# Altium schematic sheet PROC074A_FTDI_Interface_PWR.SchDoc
size 431 x 279 mm; Date: Not shown in title block; ApprovedBy: Not shown in title block; CheckedBy: Not shown in title block; Author: Not shown in title block; CompanyName: Not shown in title block; Engineer: Not shown in title block; Organization: Not shown in title block; Address1: Not shown in title block; Address2: Not shown in title block; Address3: Not shown in title block; Address4: Not shown in title block; DocumentNumber: 1; Revision: Use project parameter SCH_Rev; SheetNumber: 17; SheetTotal: 22; PageSetup: Record=PageOptions¦CenterHorizontal=True¦CenterVertical=True¦PrintScale=1.00¦XCorrection=1.00¦YCorrection=1.00¦PrintKind=0¦BorderSize=5000000¦LeftOffset=0¦BottomOffset=0¦Orientation=2¦PaperLength=1000¦PaperWidth=1000¦Scale=100¦PaperSource=15¦PrintQuality=600¦MediaType=1¦DitherType=10¦PaperKind=Letter¦PrintScaleMode=1
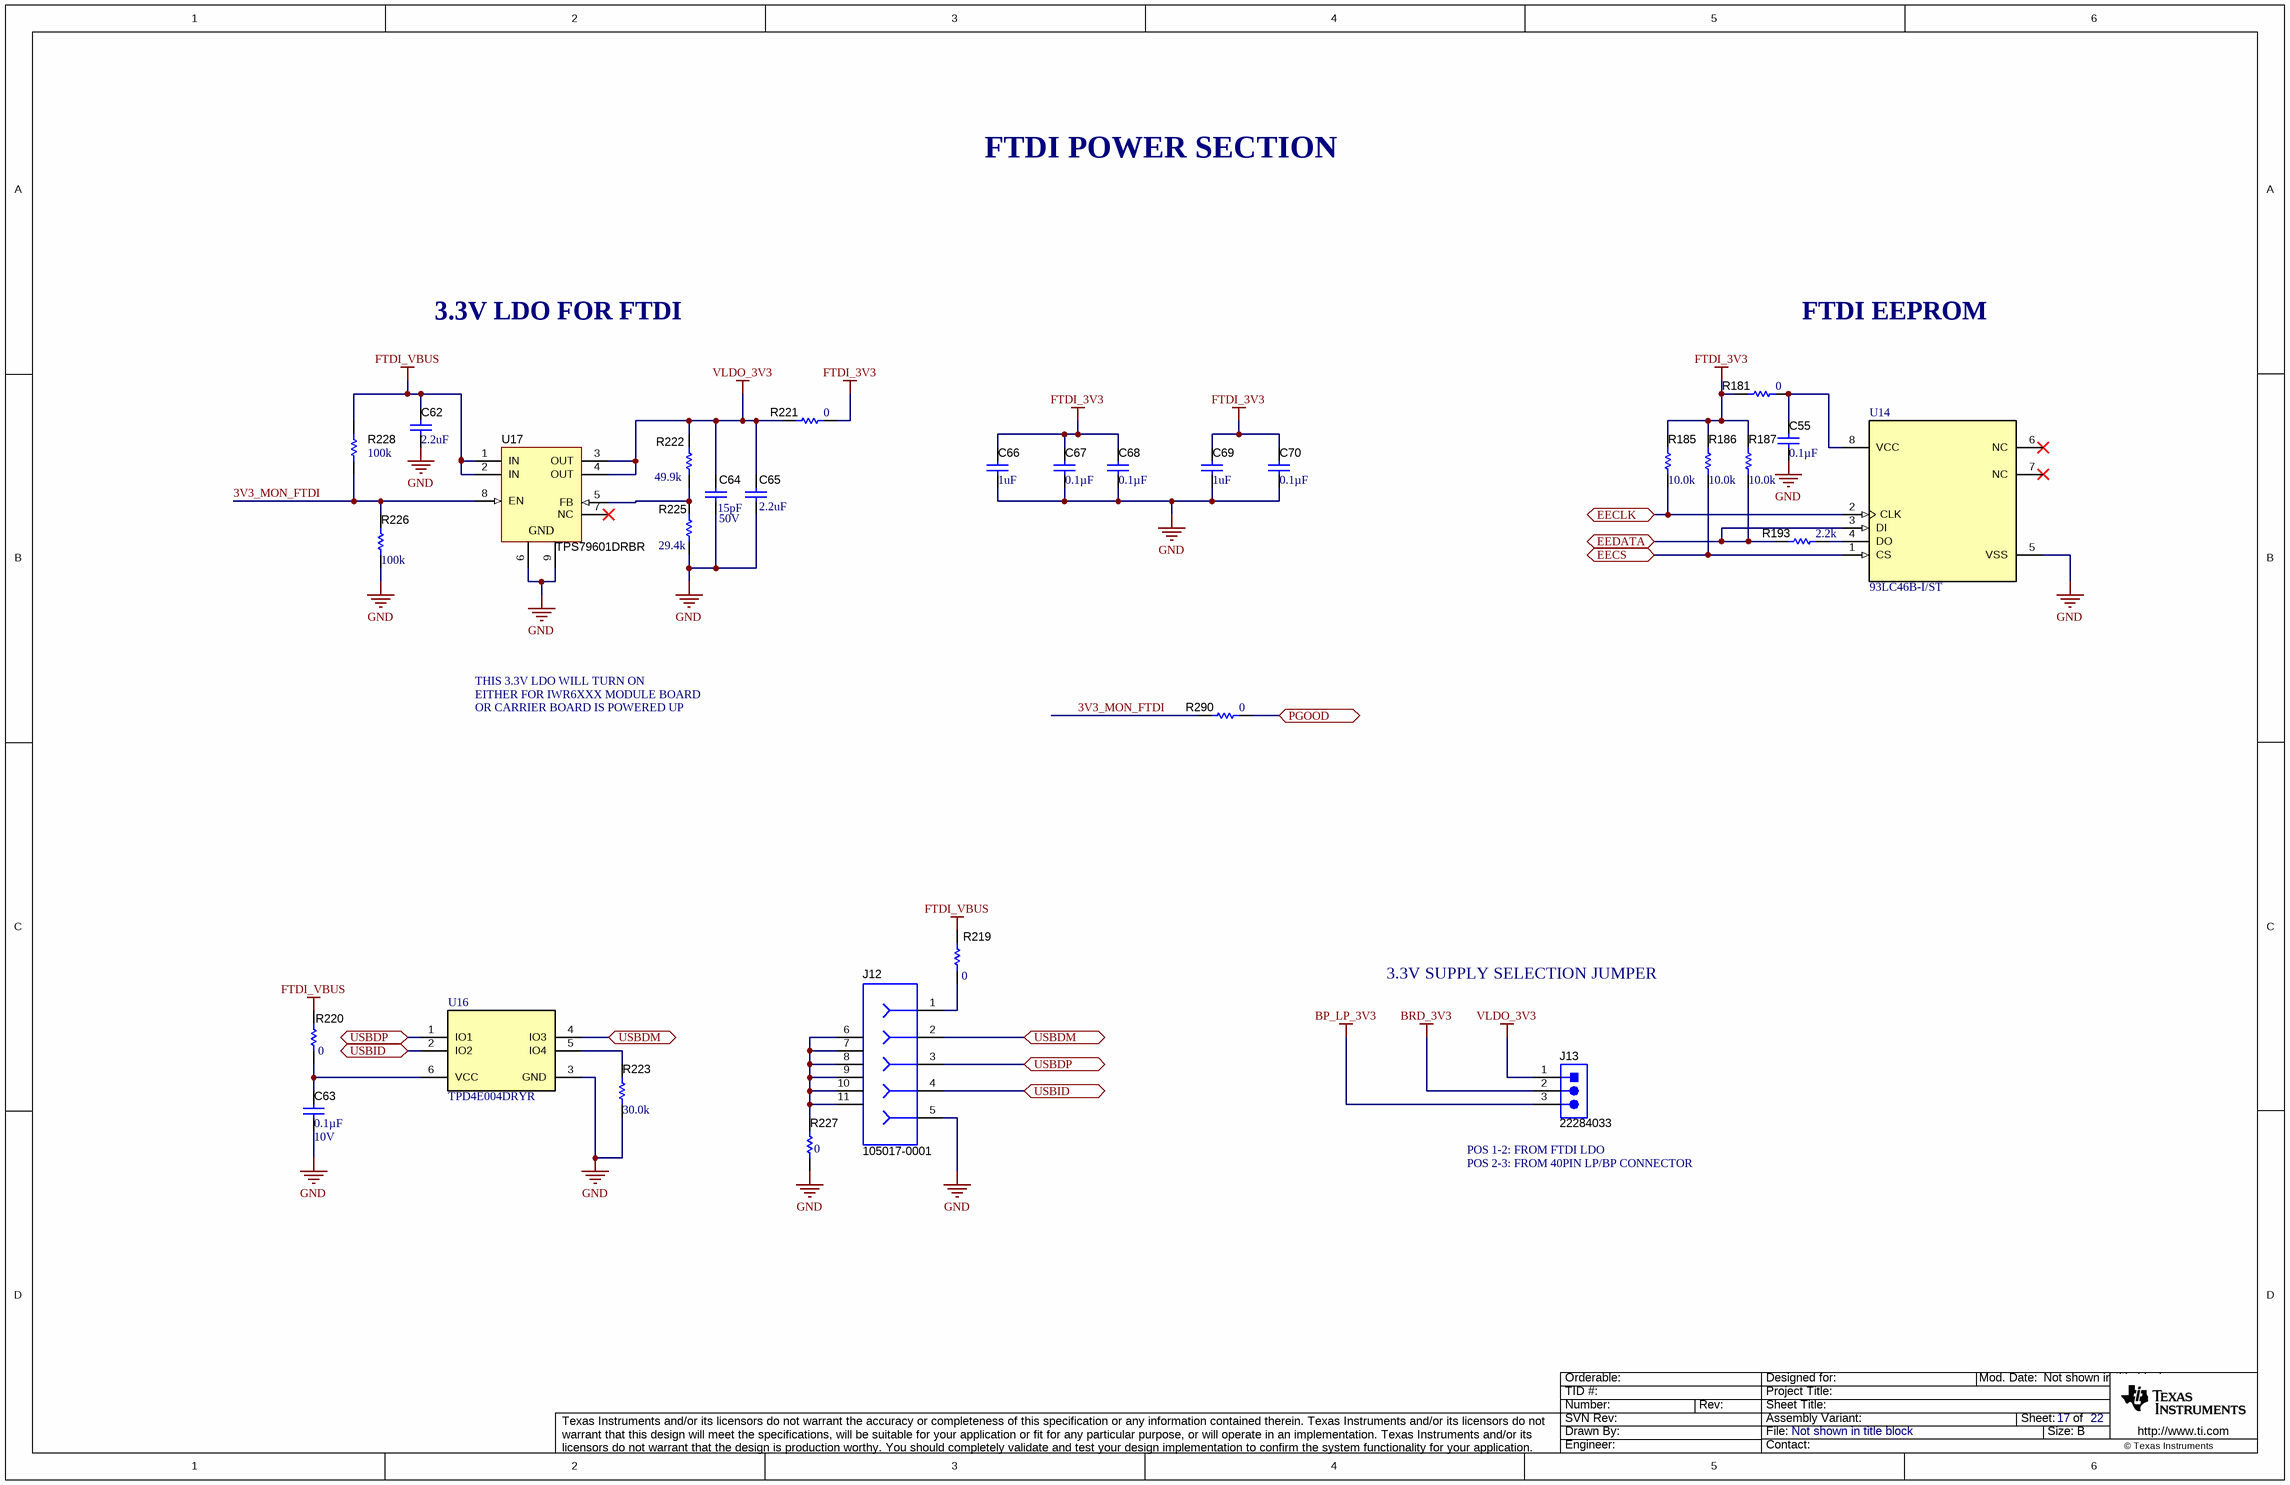
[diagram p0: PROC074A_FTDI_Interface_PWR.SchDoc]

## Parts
C55  ValueDisplayed: 0.1µF  [0402]  (hidden comment: C0402C104K8RACTU)
C62  ValueDisplayed: 2.2uF  [0402_065]  (hidden comment: C1005X7S1A225K050BC)
C63  VDC_V: 10V  ValueDisplayed: 0.1µF  [0402]  (hidden comment: C0402C104K8RACTU)
C64  VDC_V: 50V  ValueDisplayed: 15pF  [0402]  (hidden comment: 04025A150FAT2A)
C65  ValueDisplayed: 2.2uF  [0402_065]  (hidden comment: C1005X7S1A225K050BC)
C66  ValueDisplayed: 1uF  [0603]  (hidden comment: GCM188R71C105KA64D)
C67  ValueDisplayed: 0.1µF  [0402]  (hidden comment: C0402C104K8RACTU)
C68  ValueDisplayed: 0.1µF  [0402]  (hidden comment: C0402C104K8RACTU)
C69  ValueDisplayed: 1uF  [0603]  (hidden comment: GCM188R71C105KA64D)
C70  ValueDisplayed: 0.1µF  [0402]  (hidden comment: C0402C104K8RACTU)
J12  105017-0001  [CONN_105017-0001]
J13  22284033  [Molex_0022284033]
R181  ValueDisplayed: 0  [0402]  (hidden comment: ERJ-2GE0R00X)
R185  ValueDisplayed: 10.0k  [0402]  (hidden comment: CRCW040210K0FKED)
R186  ValueDisplayed: 10.0k  [0402]  (hidden comment: CRCW040210K0FKED)
R187  ValueDisplayed: 10.0k  [0402]  (hidden comment: CRCW040210K0FKED)
R193  ValueDisplayed: 2.2k  [0402]  (hidden comment: CRCW04022K20JNED)
R219  ValueDisplayed: 0  [0805_HV]  (hidden comment: CRCW08050000Z0EA)
R220  ValueDisplayed: 0  [0805]  (hidden comment: CRCW08050000Z0EA)
R221  ValueDisplayed: 0  [0805]  (hidden comment: CRCW08050000Z0EA)
R222  ValueDisplayed: 49.9k  [0402]  (hidden comment: CRCW040249K9FKED)
R223  ValueDisplayed: 30.0k  [0402]  (hidden comment: CRCW040230K0FKED)
R225  ValueDisplayed: 29.4k  [0402]  (hidden comment: CRCW040229K4FKED)
R226  ValueDisplayed: 100k  [0402]  (hidden comment: CRCW0402100KFKED)
R227  ValueDisplayed: 0  [0402]  (hidden comment: ERJ-2GE0R00X)
R228  ValueDisplayed: 100k  [0402]  (hidden comment: CRCW0402100KFKED)
R290  ValueDisplayed: 0  [0402]  (hidden comment: ERJ-2GE0R00X)
U14  93LC46B-I/ST  [TSSOP-8]
U16  TPD4E004DRYR  [DRY0006A]
U17  TPS79601DRBR  [DRB0008B]

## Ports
EECLK, EECS, EEDATA, PGOOD, USBDM, USBDP, USBID

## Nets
BP_LP_3V3: J13.3
BRD_3V3: J13.2
FTDI_3V3: C66.1 C67.1 C68.1 C69.1 C70.1 R181.2 R185.2 R186.2 R187.2 R221.2
FTDI_VBUS: C62.1 R219.2 R220.2 R228.2 U17.1(IN) U17.2(IN)
GND: C55.2 C62.2 C63.2 C64.2 C65.2 C66.2 C67.2 C68.2 C69.2 C70.2 J12.5 R223.1 R225.2 R226.1 R227.1 U14.5(VSS) U16.3(GND) U17.6(GND) U17.9(GND)
VLDO_3V3: C64.1 C65.1 J13.1 R221.1 R222.2 U17.3(OUT) U17.4(OUT)
3V3_MON_FTDI: R226.2 R228.1 R290.1 U17.8(EN)
EECLK: R185.1 U14.2(CLK) ; port EECLK
EECS: R186.1 U14.1(CS) ; port EECS
EEDATA: R187.1 R193.1 U14.3(DI) ; port EEDATA
PGOOD: R290.2 ; port PGOOD
USBDM: J12.2 U16.4(IO3) ; port USBDM
USBDP: J12.3 U16.1(IO1) ; port USBDP
USBID: J12.4 U16.2(IO2) ; port USBID
NetC55_1: C55.1 R181.1 U14.8(VCC)
NetC63_1: C63.1 R220.1 U16.6(VCC)
NetJ12_1: J12.1 R219.1
NetJ12_6: J12.6 J12.7 J12.8 J12.9 J12.10 J12.11 R227.2
NetR193_2: R193.2 U14.4(DO)
NetR222_1: R222.1 R225.1 U17.5(FB)
NetR223_2: R223.2 U16.5(IO4)

Not connected (* = marked no-connect by the designer): U14 6(NC)* 7(NC)*; U17 7(NC)*

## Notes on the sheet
- FTDI POWER SECTION
- 3.3V LDO FOR FTDI
- FTDI EEPROM
- THIS 3.3V LDO WILL TURN ON
- EITHER FOR IWR6XXX MODULE BOARD
- OR CARRIER BOARD IS POWERED UP
- 3.3V SUPPLY SELECTION JUMPER
- (near J13) POS 1-2: FROM FTDI LDO
- POS 2-3: FROM 40PIN LP/BP CONNECTOR

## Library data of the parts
C55 C67 C68 C70 = CMP-0078241-1: CAP, CERM, 0.1 µF, 10 V,+/- 10%, X7R, 0402; Manufacturer: Kemet; TaMin_C: -55°C; Polarized: N; SizeAreaWB_mm2: 3; U/M: EA; Value: 0.1uF; TaMax_C: 125°C; SizeZ_mm: 0.6; SizeX_mm: 1; SizeY_mm: 0.5; Value2: 10V; CompType: Capacitor; Cap_F: 100nF; AEC Category: Q200
C62 C65 = CMP-0006302-2: CAP, CERM, 2.2 uF, 10 V, +/- 10%, X7S, 0402; Manufacturer: TDK; TaMin_C: -55°C; ESR_ohm: 5.925m; Polarized: N; SizeAreaWB_mm2: 3; Value1: 0.005925 ohm; U/M: EA; Value: 2.2uF; TaMax_C: 125°C; SizeZ_mm: 0.65; SizeX_mm: 1; SizeY_mm: 0.5; Value2: 10V; CompType: Capacitor; Cap_F: 2.2µF; IRMS_A: 2.05591A; AEC Category: Q200
C63 = CMP-0078241-1: CAP, CERM, 0.1 µF, 10 V,+/- 10%, X7R, 0402; Manufacturer: Kemet; TaMin_C: -55°C; Polarized: N; SizeAreaWB_mm2: 3; U/M: EA; Value: 0.1uF; TaMax_C: 125°C; SizeZ_mm: 0.6; SizeX_mm: 1; SizeY_mm: 0.5; Cap_F: 100nF; AEC Category: Q200
C64 = CMP-0078217-1: CAP, CERM, 15 pF, 50 V,+/- 1%, C0G/NP0, 0402; Manufacturer: AVX; TaMin_C: -55°C; Polarized: N; Green_Lifecycle: Not Set; SizeAreaWB_mm2: 3; Green_REACh: Incomplete; U/M: EA; Value: 15pF; TaMax_C: 125°C; SizeZ_mm: 0.6; SizeX_mm: 1; SizeY_mm: 0.5; AEC Category: Q200
C66 C69 = CMP-0007136-5: CAP, CERM, 1 uF, 16 V, +/- 10%, X7R, AEC-Q200 Grade 1, 0603; Manufacturer: MuRata; TaMin_C: -55°C; Polarized: N; SizeAreaWB_mm2: 4.68; Value1: Unknown; U/M: EA; Value: 1uF; TaMax_C: 125°C; SizeZ_mm: 1; SizeX_mm: 1.6; SizeY_mm: 0.8; Value2: 16V; SizeArea_mm2: 1.28; CompType: Capacitor; AEC Qualified: Y; Cap_F: 1µF; AEC Category: Q200
J12 = CMP-0055293-1: Connector, Receptacle, Micro-USB Type B, R/A, Bottom Mount SMT; Manufacturer: Molex; CNHeader: FALSE; Green_Lifecycle: Active; Gender: Female; Green_REACh: Passed; CompType: USB; CT: TRUE
J13 = CMP-0055332-1: Header, 2.54mm, 3x1, Tin, TH; Manufacturer: Molex; CNHeader: TRUE; Current_A: 4A; Shrouded: N; Gender: Male; Voltage_V: 250V; Row_Count: 1; Pitch_mm: 2.54; CT: FALSE; Cert_UL: Y
R181 R227 R290 = CMP-0026992-3: RES, 0, 5%, 0.1 W, AEC-Q200 Grade 0, 0402; Manufacturer: Panasonic; Power_W: 100mW; TempCo: 600 ppm/C; Value_Code: 0000; Value: 0; EIA_Code: E24; SizeX_mm: 1; SizeY_mm: 0.5; SizeZ_mm: 0.6; Value2: 0.1W; AEC Qualified: Y; VDC_V: 50V; AEC Category: Q200; SizeAreaWB_mm2: 3
R185-R187 = CMP-0025958-3: RES, 10.0 k, 1%, 0.063 W, AEC-Q200 Grade 0, 0402; Manufacturer: Vishay-Dale; Power_W: 63mW; TempCo: 100 ppm/C; Value_Code: 10k0; Value: 10.0k; EIA_Code: E96; Res_ohm: 10k; SizeX_mm: 1; SizeY_mm: 0.5; SizeZ_mm: 0.6; Value2: 0.063W; AEC Qualified: Y; VDC_V: 50V; AEC Category: Q200; AEC Grade: 0
R193 = CMP-0026890-5: RES, 2.2 k, 5%, 0.063 W, AEC-Q200 Grade 0, 0402; Manufacturer: Vishay-Dale; Power_W: 63mW; TempCo: 200 ppm/C; Value_Code: 2k20; Value: 2.2k; EIA_Code: E24; SizeX_mm: 1; SizeY_mm: 0.5; SizeZ_mm: 0.6; Value2: 0.063W; AEC Qualified: Y; VDC_V: 50V; AEC Category: Q200; AEC Grade: 0
R219-R221 = CMP-0020442-3: RES, 0, 5%, 0.125 W, AEC-Q200 Grade 0, 0805; Manufacturer: Vishay-Dale; Power_W: 125mW; TempCo: 200 ppm/C; Value_Code: 0000; Value: 0; EIA_Code: E24; SizeX_mm: 2; SizeY_mm: 1.25; SizeZ_mm: 1.45; Value2: 0.125W; SizeArea_mm2: 2.5; AEC Qualified: Y; VDC_V: 150V; AEC Category: Q200
R222 = CMP-0026403-2: RES, 49.9 k, 1%, 0.063 W, AEC-Q200 Grade 0, 0402; Manufacturer: Vishay-Dale; Power_W: 63mW; TempCo: 100 ppm/C; Value_Code: 49k9; Value: 49.9k; EIA_Code: E96; SizeX_mm: 1; SizeY_mm: 0.5; SizeZ_mm: 0.6; Value2: 0.063W; AEC Qualified: Y; VDC_V: 50V; AEC Category: Q200; AEC Grade: 0
R223 = CMP-0078244-2: RES, 30.0 k, 1%, 0.063 W, AEC-Q200 Grade 0, 0402; Manufacturer: Vishay-Dale; Power_W: 63mW; Green_Lifecycle: Active; TempCo: 100 ppm/C; Value_Code: 30k0; Green_REACh: Passed; Value: 30.0k; Res_ohm: 30k; SizeX_mm: 1; SizeY_mm: 0.5; SizeZ_mm: 0.6; Value2: 0.063W; AEC Qualified: Y; VDC_V: 50V; AEC Grade: 0; AEC Category: Q200
R225 = CMP-0026225-2: RES, 29.4 k, 1%, 0.063 W, AEC-Q200 Grade 0, 0402; Manufacturer: Vishay-Dale; Power_W: 63mW; TempCo: 100 ppm/C; Value_Code: 29k4; Value: 29.4k; EIA_Code: E96; SizeX_mm: 1; SizeY_mm: 0.5; SizeZ_mm: 0.6; Value2: 0.063W; AEC Qualified: Y; VDC_V: 50V; AEC Category: Q200; AEC Grade: 0
R226 = CMP-0025950-3: RES, 100 k, 1%, 0.063 W, AEC-Q200 Grade 0, 0402; Manufacturer: Vishay-Dale; Power_W: 63mW; TempCo: 100 ppm/C; Value: 100k; EIA_Code: E96; SizeX_mm: 1; SizeY_mm: 0.5; SizeZ_mm: 0.6; Value2: 0.063W; AEC Qualified: Y; VDC_V: 50V; AEC Category: Q200; AEC Grade: 0
R228 = CMP-0025950-3: RES, 100 k, 1%, 0.063 W, AEC-Q200 Grade 0, 0402; Manufacturer: Vishay-Dale; Power_W: 63mW; TempCo: 100 ppm/C; Value: 100k; EIA_Code: E96; SizeX_mm: 1; SizeY_mm: 0.5; SizeZ_mm: 0.6; Value2: 0.063W; CompType: Resistor; AEC Qualified: Y; VDC_V: 50V; AEC Category: Q200; AEC Grade: 0; INSTALLATION: DNP
U14 = CMP-0081524-1: 1K Microwire Compatible Serial EEPROM, TSSOP-8; Manufacturer: Microchip; SizeArea_mm2: 19.2; SizeAreaWB_mm2: 42; SizeY_mm: 3; SizeZ_mm: 1.2; SizeX_mm: 6.4
U16 = CMP-0043115-2: ESD-Protection Array for High-Speed Data Interfaces, 4 Channels, -40 to +85 degC, 6-pin SON (DRY), Green (RoHS & no Sb/Br); Manufacturer: Texas Instruments; IO Leakage Current(nA): 1; USB High Speed: TRUE; IO Capacitance(Typ)(pF): 1.6; SubFamily: ESD Solution; IEC 61000-4-2 Contact(+/- kV): 8; Breakdown Voltage(Min)(V): 6; IEC 61000-4-2 Air-Gap(+/- kV): 12; AEC Category: Q200; AEC Qualified: N; CompType: IC; SizeAreaWB_mm2: 4.9; SizeArea_mm2: 1.45; SizeX_mm: 1.0; SizeZ_mm: 0.6
U17 = CMP-0036402-3: Single Output High PSRR LDO, 1 A, Adjustable 1.2 to 5.5 V Output, 2.7 to 5.5 V Input, 8-pin SON (DRB), -40 to 125 degC, Green (RoHS & no Sb/Br); Manufacturer: Texas Instruments; Vin(Min)(V): 2.7; Vout Adj(Max)(V): 5.5; Vout Adj(Min)(V): 1.2; Accuracy(%): 2; SubFamily: Single Channel LDO; Iq(Typ)(mA): 0.26; Vdo(Typ)(mV): 250; Iout(Max)(A): 1; AEC Category: Q200; AEC Qualified: N; CompType: IC; SizeAreaWB_mm2: 16.0; SizeArea_mm2: 9.0; SizeX_mm: 3.0; SizeZ_mm: 1.0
